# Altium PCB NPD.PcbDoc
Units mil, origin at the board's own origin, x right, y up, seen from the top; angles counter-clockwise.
Board outline 2010.03 x 1675.03 mil, 4 copper layers (Top Layer, VCC, VEE, Bottom Layer); 32 components, 16 nets, 87 pads, 24 vias.
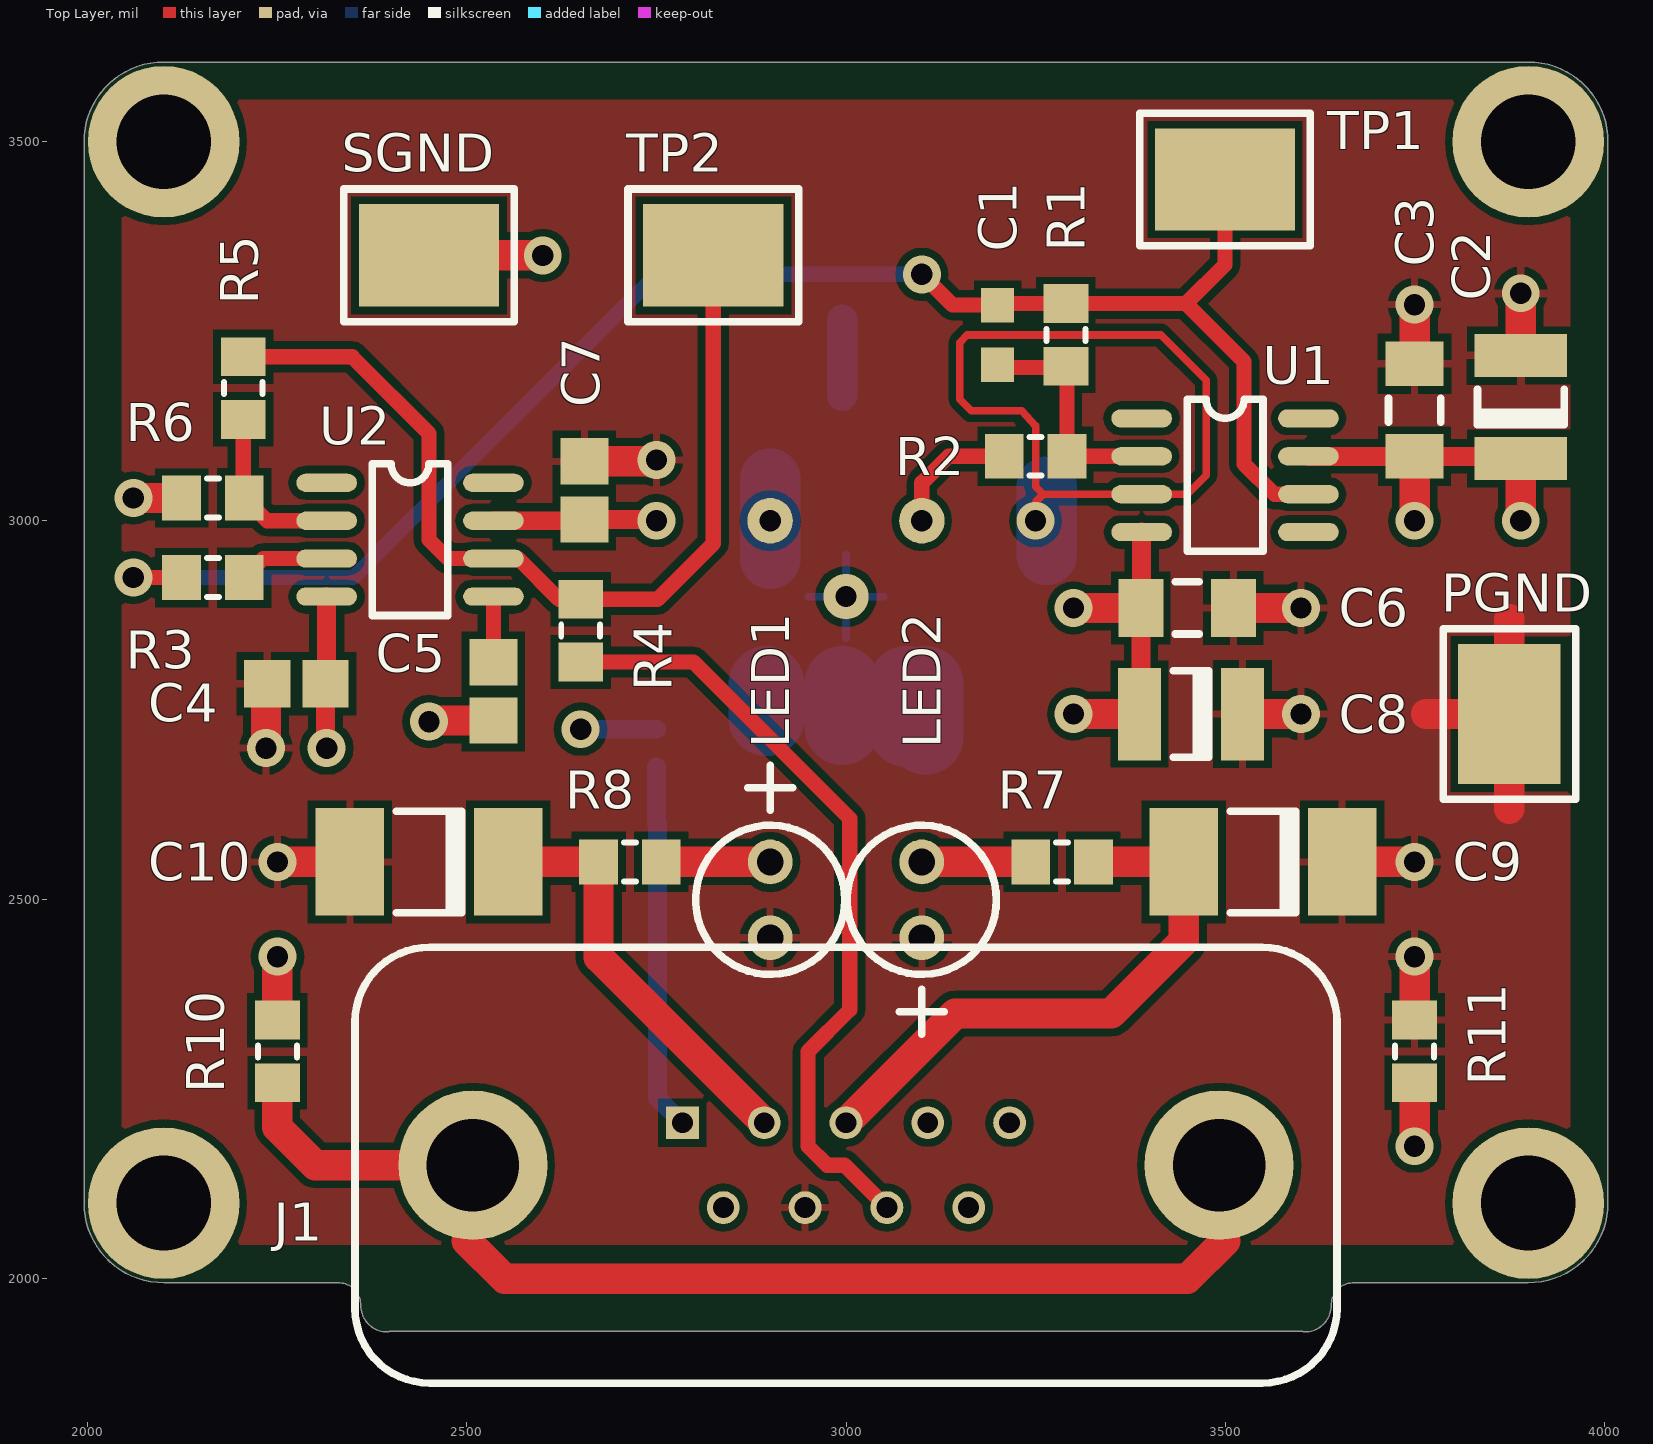
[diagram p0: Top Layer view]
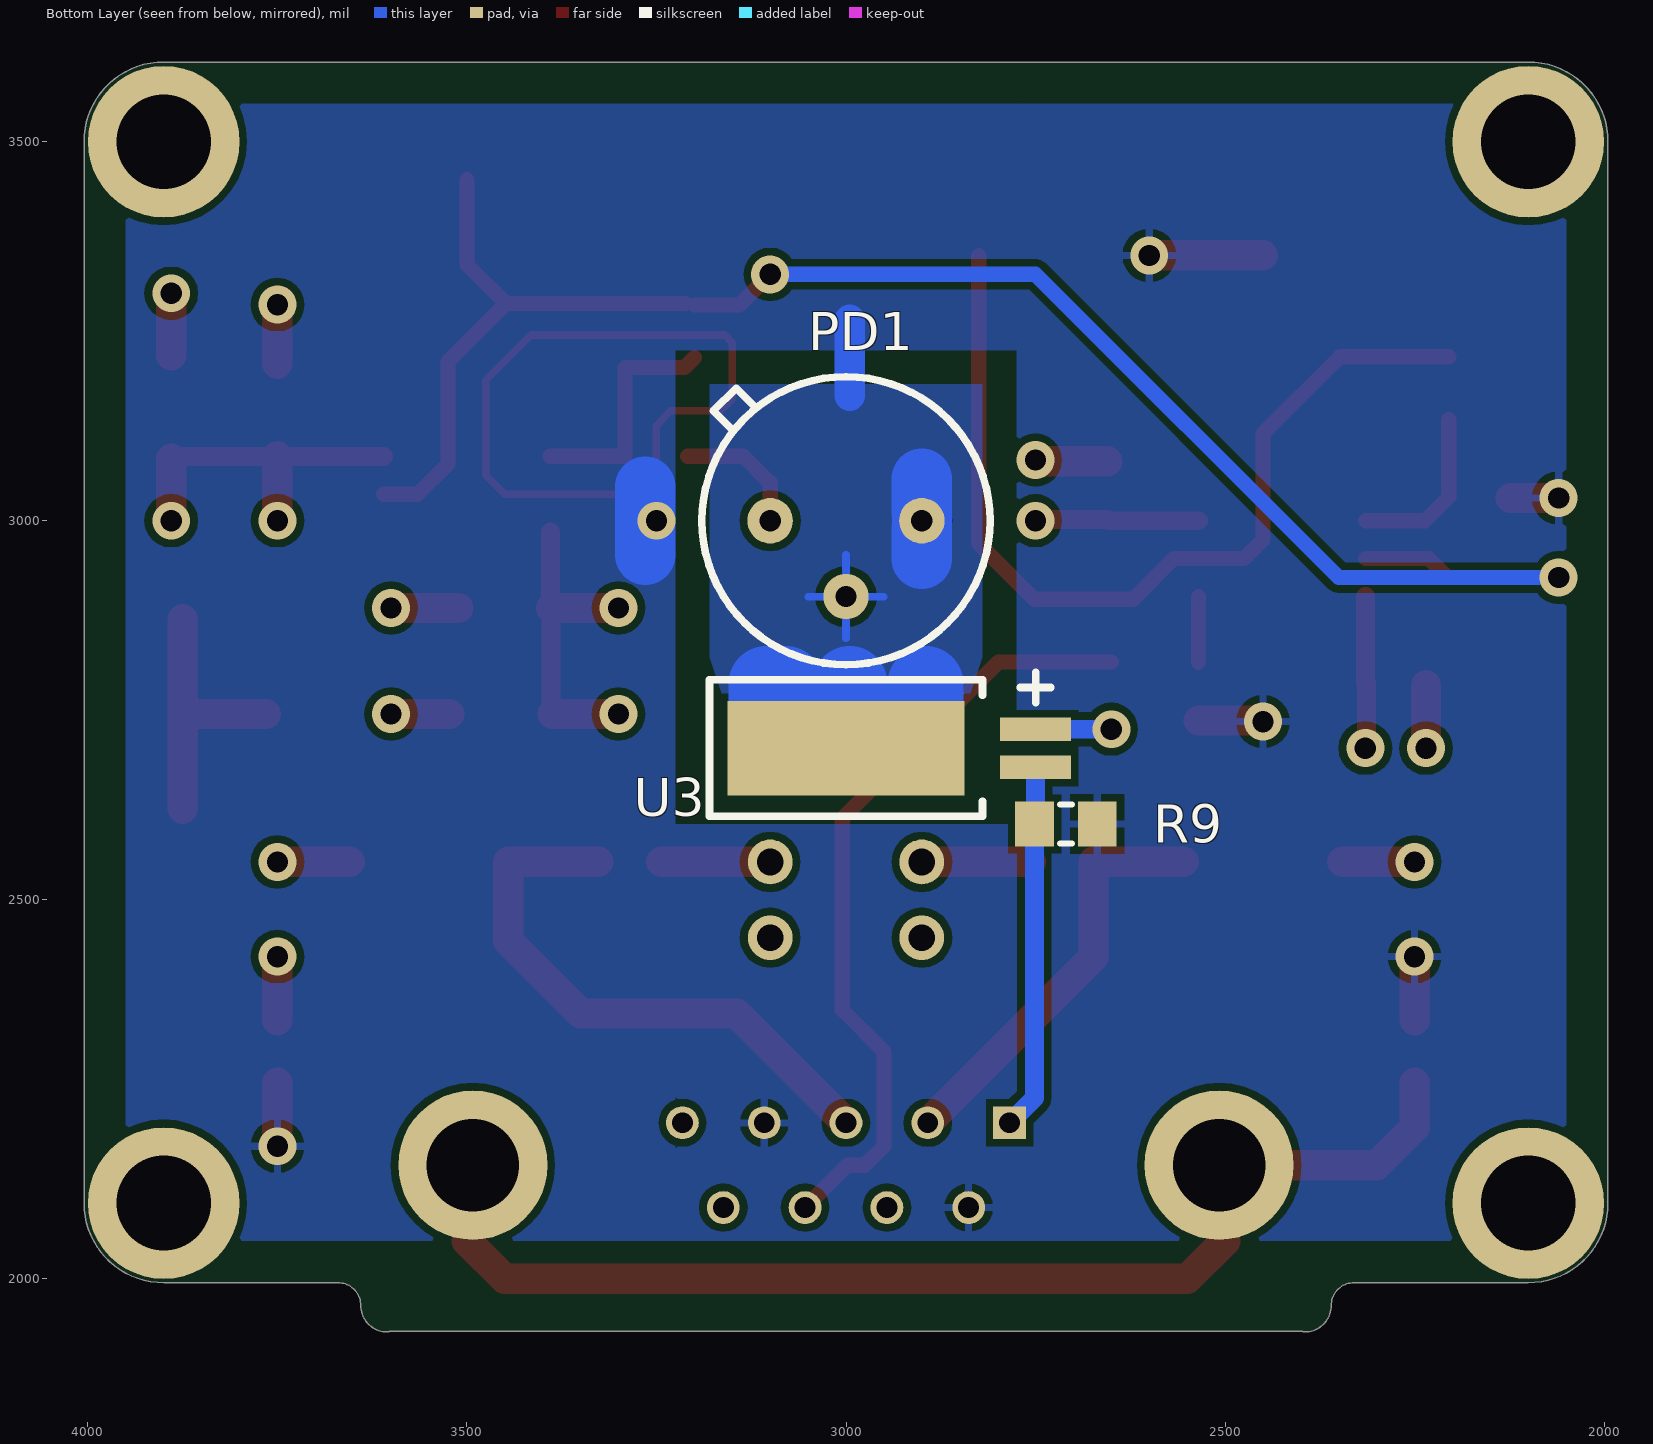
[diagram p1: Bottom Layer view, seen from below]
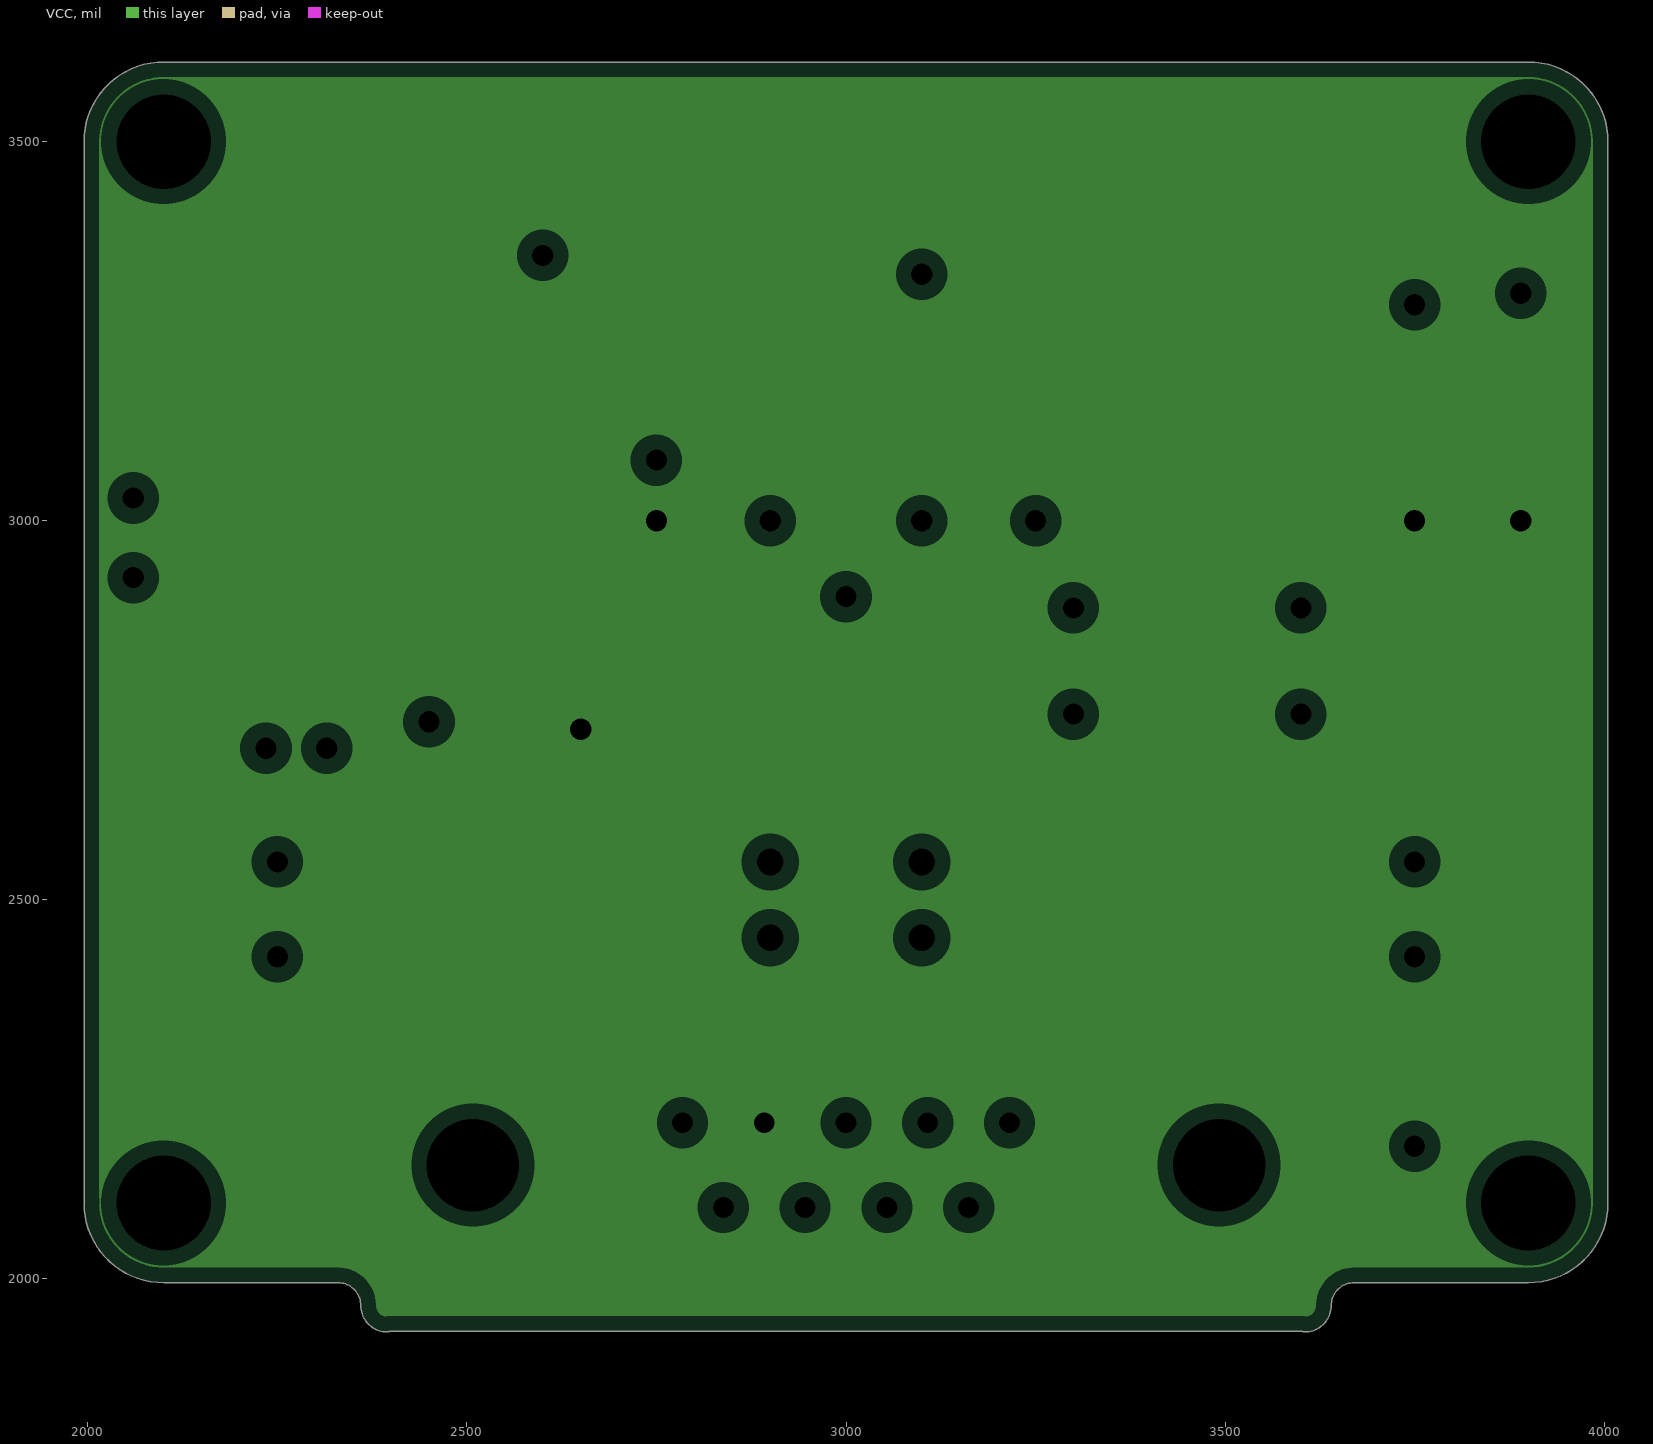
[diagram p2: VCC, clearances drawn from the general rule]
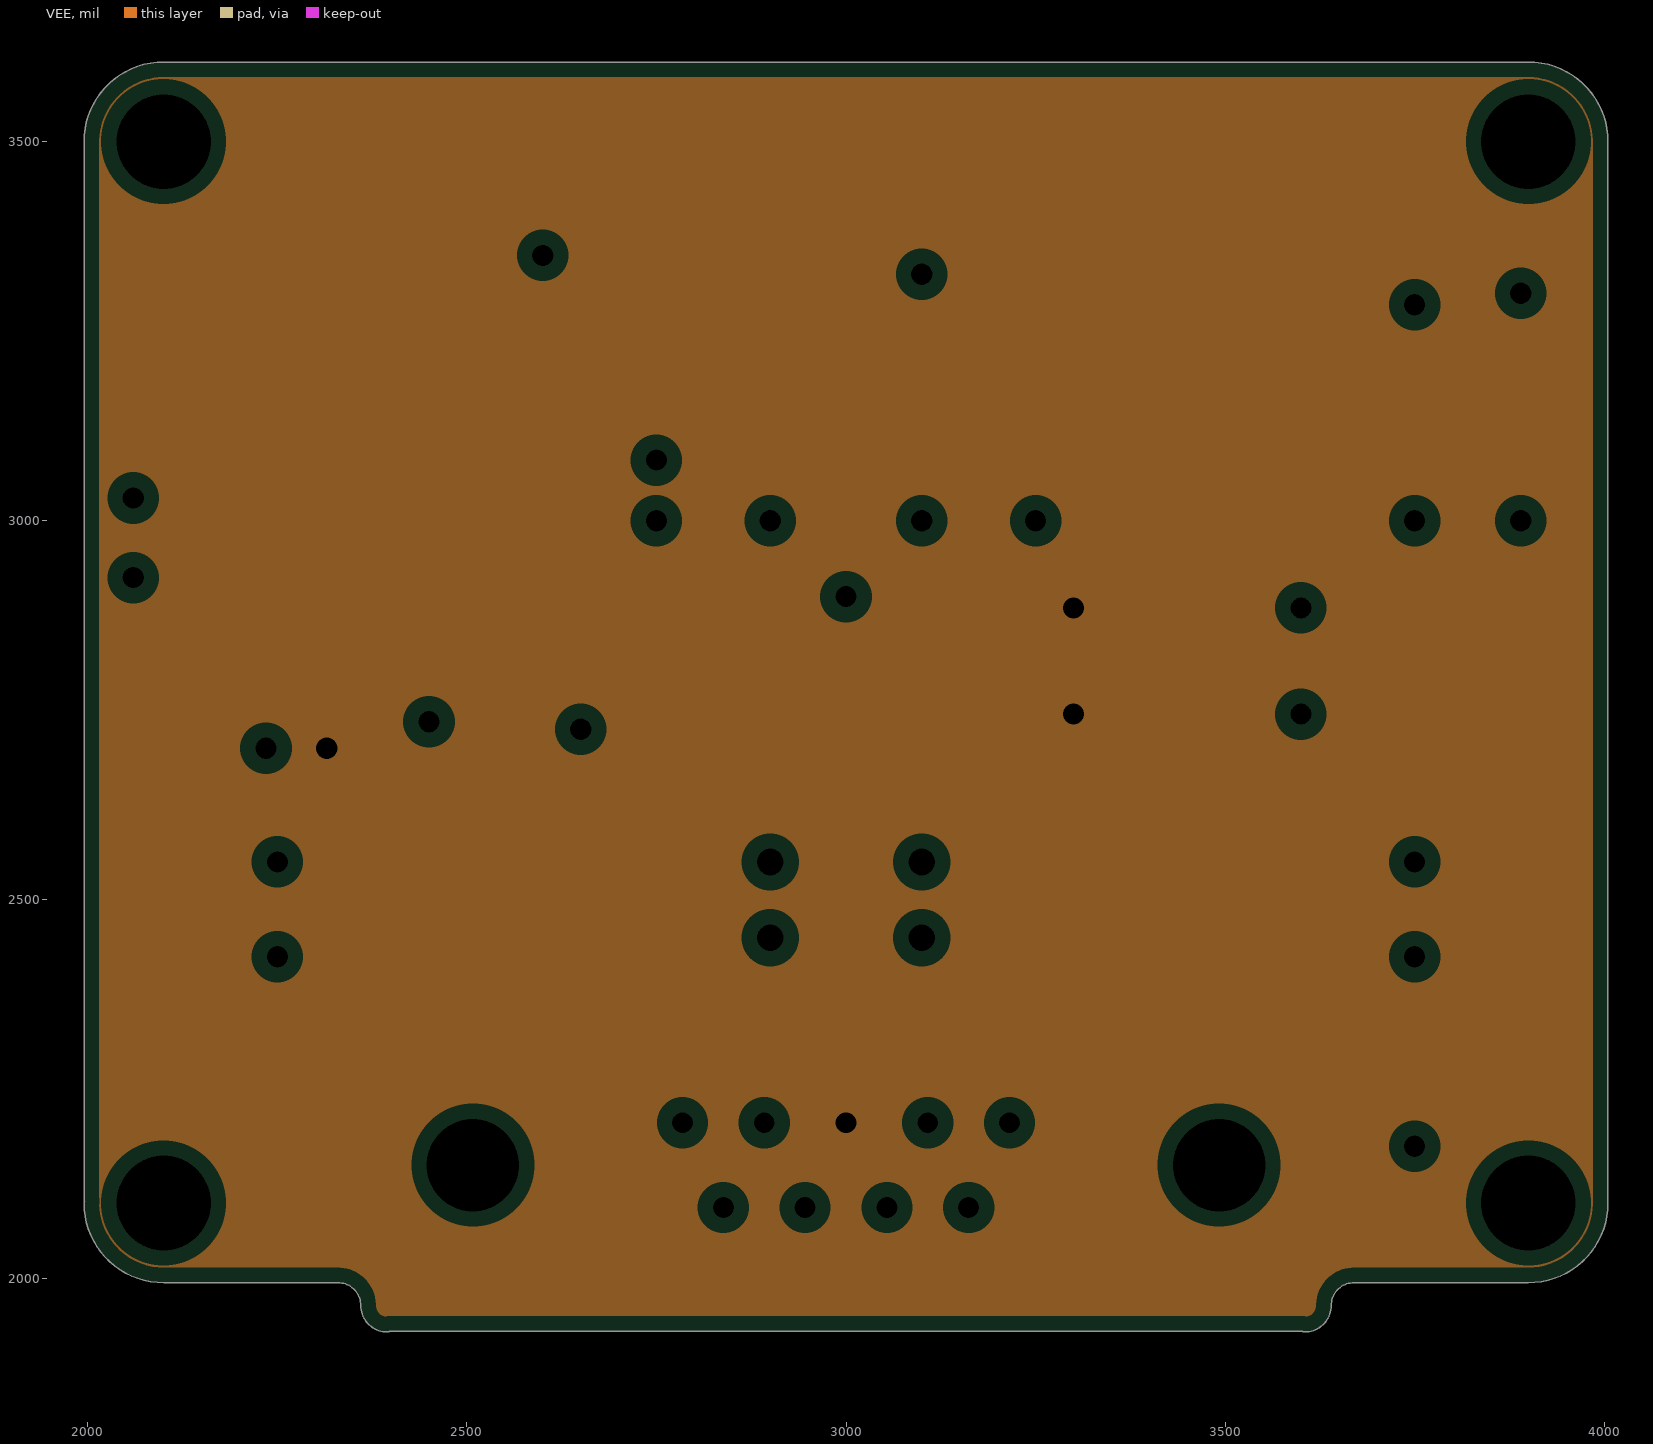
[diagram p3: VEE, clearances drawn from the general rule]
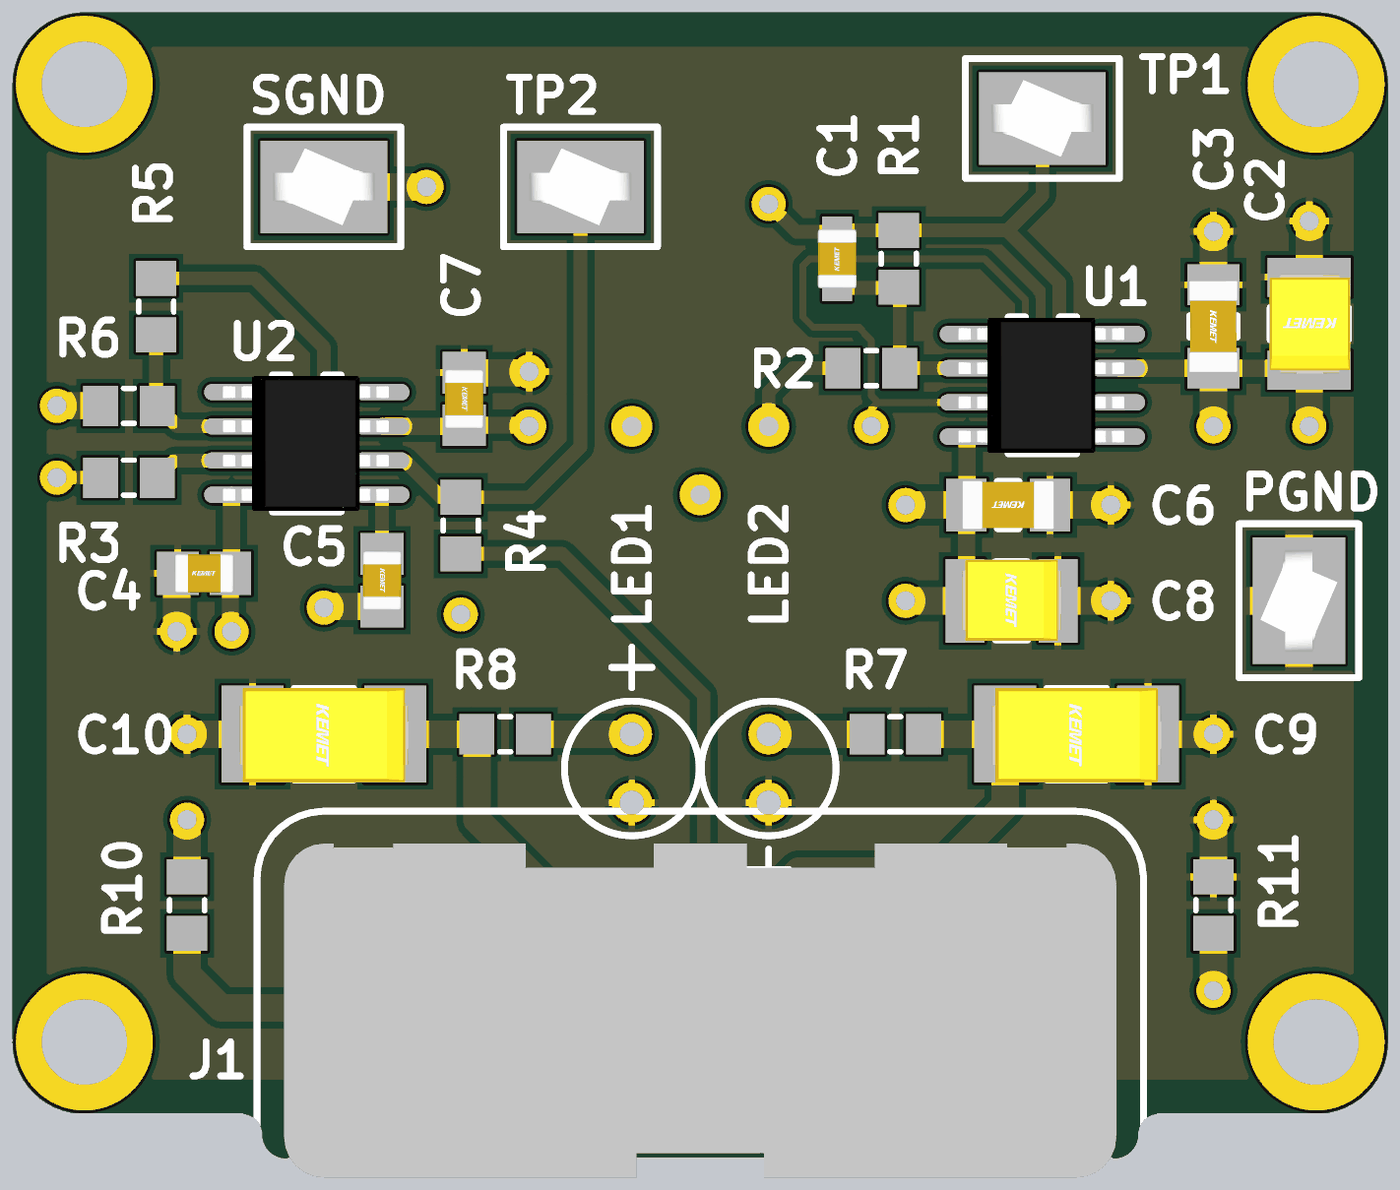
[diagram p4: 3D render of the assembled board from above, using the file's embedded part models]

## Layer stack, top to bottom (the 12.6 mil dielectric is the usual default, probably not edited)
Top Layer: signal copper 1.4
Dielectric: core 12.6, FR-4, Dk 4.8
VCC: plane copper 1.4, net VCC
Dielectric: prepreg 12.6, FR-4, Dk 4.8
VEE: plane copper 1.4, net VEE
Dielectric: core 12.6, FR-4, Dk 4.8
Bottom Layer: signal copper 1.4

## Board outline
2100,1994.98 2330,1994.98 cw(c2330,1965) 2359.99,1965 ccw(c2395,1965) 2395,1929.98 ccw(c2395,1935) 2398.09,1931.05 3601.91,1931.05 ccw(c3605,1935) 3605,1929.98 ccw(c3605,1965) 3640.01,1965 cw(c3670,1965) 3670,1994.98 3900,1994.98 ccw(c3900,2100) 4005.01,2100 4005.01,3500 ccw(c3900,3500) 3900,3605.01 2100,3605.01 ccw(c2100,3500) 1994.98,3500 1994.98,2105 ccw(c2000,2105) 1995.65,2102.5 ccw(c2000,2100) 1994.98,2100 ccw(c2100,2100)

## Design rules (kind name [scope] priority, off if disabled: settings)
Clearance [All] p1: gap=10
HoleSize [All] p1: absolutevalues=TRUE maxlimit=200 minlimit=1 maxpercent=80.000 minpercent=20.000
PlaneClearance [All] p1: clearance=20
PlaneConnect [All] p1: planeconnectstyle=Relief reliefexpansion=20 reliefentries=4 reliefconductorwidth=10 reliefairgap=10
PolygonConnect [All] p1: connectstyle=Relief reliefconductorwidth=10 reliefentries=4 polygonreliefangle="90 Angle"
RoomDefinition Schematic [InComponentClass('Schematic')] p1: confinementstyle=ConfineOut formatcopy=TRUE lockcomponents=FALSE outline 2000,1930 2050,1930 2050,1950 2000,1950
RoutingVias [All] p1: holewidth=28 width=50 viastyle="Through Hole" minholewidth=28 minwidth=50 maxholewidth=28 maxwidth=50
SilkscreenOverComponentPads [All] p1: minsilkscreentomaskgap=10
SolderMaskExpansion [All] p1: expansion=4
Width [All] p1: maxlimit=200 minlimit=10 preferedwidth=10 minimp=50.000000 maximp=50.000000 favimp=50.000000
24 further rules are at their usual default settings.

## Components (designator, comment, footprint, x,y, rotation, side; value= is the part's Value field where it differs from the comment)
C1 "2.7 pF" "Kemet 0805, low density" 3200,3245 r90 top
C2 "3.3 uF" "Kemet 3528-21" 3890,3150 r90 top
C3 "0.1 uF" "Kemet EIA 1206" 3750,3146 r270 top
C4 "0.1 uF" "0805 low density" 2275,2785 r0 top
C5 "68 pF" "Kemet EIA 0805" 2535,2775 r270 top
C6 "0.1 uF" "Kemet EIA 1206" 3450,2885 r180 top
C7 "0.1 uF" "0805 low density" 2655,3040 r270 top
C8 "3.3 uF" "Kemet 3528-21" 3455,2745 r180 top
C9 "10 uF" "Kemet 6032-28" 3550,2550 r180 top
C10 "10 uF" "Kemet 6032-28" 2450,2550 r180 top
J1 "Dsub 9 male" 1-338309 3000,2150 r0 top
LED1 "3mm LED" WP424GDT 2900,2500 r270 top
LED2 "3mm LED" WP424GDT 3100,2500 r90 top
PD1 "C30665GH" TO-5 3000,3000 r0 bottom
PGND "GROUND TEST POINT" "COMPACT TEST POINT" 3875,2745 r90 top (schematic designator TP3)
R1 "20.0k" "Vishay TNPW0805 e3 low density" 3290,3245 r90 top
R2 "ZERO" "Vishay TNPW0805 e3 low density" 3250,3085 r0 top
R3 "ZERO" "Vishay TNPW0805 e3 low density" 2165,2925 r0 top
R4 "ZERO" "Vishay TNPW0805 e3 low density" 2650,2855 r270 top
R5 "ZERO" "Vishay TNPW0805 e3 low density" 2205,3175 r90 top
R6 "ZERO" "Vishay TNPW0805 e3 low density" 2165,3030 r0 top
R7 "2.00k" "Vishay TNPW0805 e3 low density" 3285,2550 r0 top
R8 "2.00k" "Vishay TNPW0805 e3 low density" 2715,2550 r180 top
R9 "10.0k" "Vishay TNPW0805 e3 low density" 2710,2600 r0 bottom
R10 "ZERO" "Vishay TNPW0805 e3 low density" 2250,2300 r270 top
R11 "ZERO" "Vishay TNPW0805 e3 low density" 3750,2300 r270 top
SGND "GROUND TEST POINT" "COMPACT TEST POINT" 2450,3350 r0 top (schematic designator TP4)
TP1 "TEST POINT" "COMPACT TEST POINT" 3500,3450 r0 top
TP2 "TEST POINT" "COMPACT TEST POINT" 2825,3350 r0 top
U1 "THS4631D" SO-8 3500,3060 r0 top
U2 "AD829ARZ" SO-8 2425,2975 r0 top
U3 "AD590MF" AD590 3000,2700 r0 bottom

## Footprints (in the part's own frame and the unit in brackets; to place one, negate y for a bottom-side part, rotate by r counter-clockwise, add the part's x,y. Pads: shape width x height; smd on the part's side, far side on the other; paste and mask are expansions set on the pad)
1-338309 [mm] "DB9 male, vertical plug header with solder contacts"
  rect 1.1x1.1 hole 0.7: 1(-5.48,1.42)
  round 1.1 hole 0.7: 2(-2.74,1.42) 3(0,1.42) 4(2.74,1.42) 5(5.48,1.42) 6(-4.11,-1.42) 7(-1.37,-1.42) 8(1.37,-1.42) 9(4.11,-1.42)
  round 5 hole 3.1: 10(-12.5,0) 11(12.5,0)
  silkscreen extent -16.45,-7.3 16.45,7.3, body extent -15.45,-6.3 15.45,6.1, height 12.1
"0805 low density" [mm] "0805 chip capacitor, 2 leads, body 2.0x1.3 mm, low density"
  rect 1.55x1.6 smd: 1(-0.975,0) 2(0.975,0)
  body extent -1.1,-0.73 1.1,0.72, height 0.87
AD590 [mil] "2 lead ceramic flat package (F-2)"
  rect 93.75x31.25 smd: 1(-250,-25) 2(-250,25)
  rect 312.5x125 smd: 3(0,0)
  silkscreen extent -270,-100 180,90, body extent -300,-46 105,46, height 50
"COMPACT TEST POINT" [mil] "compact SMT test point"
  rect 185x135 smd: 1(0,0)
  silkscreen extent -112,-88 112,88, body extent -75,-56 75,56, height 91
"Kemet 0805, low density" [mm] "0805 low density chip capacitor"
  rect 1.15x1.1 smd: 1(-1,0) 2(1,0)
  body extent -1.1,-0.73 1.1,0.72, height 0.87
"Kemet 3528-21" [mm] "2 lead, polarised chip capacitor, body 3.5 mm x 2.8 mm, IPC low density"
  rect 1.45x3.1 smd: 1(-1.725,0) 2(1.725,0)
  silkscreen extent -0.6,-1.45 0.6,1.45, body extent -1.85,-1.52 1.85,1.48, height 2.11
"Kemet 6032-28" [mm] "2 lead, polarised chip capacitor, body 6.0 mm x 3.2 mm, IPC low density"
  rect 2.3x3.6 smd: 1(-2.65,0) 2(2.65,0)
  silkscreen extent -1.1,-1.7 1.1,1.7, body extent -3.15,-1.71 3.15,1.79, height 2.81
"Kemet EIA 0805" [mm] "2 lead, chip capacitor, body 2.00 mm x 1.25mm, IPC low density"
  rect 1.55x1.6 smd: 1(-0.975,0) 2(0.975,0)
  body extent -1.09,-0.72 1.11,0.72, height 0.87
"Kemet EIA 1206" [mm] "2 lead, chip capacitor, body 3.2 mm x 1.60 mm, IPC low density"
  rect 1.5x1.95 smd: 1(-1.55,0) 2(1.549,0)
  silkscreen extent -0.4,-0.87 0.4,0.87, body extent -1.7,-0.9 1.7,0.9, height 0.88
SO-8 [mil] "8 pin small outline package"
  oval 80x24 smd: 1(-110,75) 2(-110,25) 3(-110,-25) 4(-110,-75) 5(110,-75) 6(110,-25) 7(110,25) 8(110,75)
  silkscreen extent -50,-100 50,100, body extent -123,-98 120,98, height 79
TO-5 [mil] "3 pin TO-5"
  round 60 hole 28: 1(100,0) 2(0,100) 3(-100,0)
  silkscreen extent -190,-190 190,190, body extent -179,-180 179,180, height 167
"Vishay TNPW0805 e3 low density" [mm] "chip resistor, 2 lead, 0805 body 2.0 x 1.3 mm, IPC low density"
  rect 1.3x1.5 smd: 1(-1.05,0) 2(1.05,0)
  silkscreen extent -0.2,-0.65 0.2,0.65, body extent -1,-0.63 1,0.63, height 0.45
WP424GDT [mm] "T-1 (3 mm) cylindrical LED lamp"
  round 1.5 hole 0.9: A(-1.27,0) K(1.27,0)
  silkscreen extent -4.5,-2.5 2.5,2.5, body extent -1.7,-1.7 1.69,1.69, height 6

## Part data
C1: library part "2.7 pF, 50 V, 0805 ceramic capacitor", "2.7 pF, +/- 0.1 pF C0G ceramic chip capacitor"
C2 C8: library part "3.3 uF, 35 V, 10% tantalum capacitor", "SMD chip tantalum capacitor"
C3 C6: library part "0.1 uF, 50 V, 1206 ceramic capacitor", "0.1 uF, +/- 1% U2J ceramic chip capacitor"
C4 C7: library part "0.1 uF, 5% 50 V, 0805 ceramic capacitor", "0.1 uF, +/- 5% X7R ceramic chip capacitor"
C5: library part "68 pF, 50 V, 0805 ceramic capacitor", "68 pF, +/- 1% C0G ceramic chip capacitor"
C9 C10: library part "10 uF, 25 V, 10% tantalum capacitor", "SMD chip tantalum capacitor"
J1: "Dsub 9 male, vertical"
PD1: "3 mm InGaAs photodiode"
R1: library part "20.0k ohm, +/- 0.05%", "20.0k ohm, +/- 0.05% thin film chip resistor"
R2 R3 R4 R5 R6 R10 R11: library part "ZERO OHMS", "1206 zero ohm jumper"
R7 R8: library part "2.00k ohm, +/- 0.05%", "2.00k ohm, +/- 0.05% thin film chip resistor"
R9: library part "10.0k ohm, +/- 0.05%", "10.0k ohm, +/- 0.05% thin film chip resistor"
TP1 TP2: library part TP, "test point"
U1: "high voltage, high slew rate, wideband FET input operational amplifier"
U2: "high speed, low noise video op amp"
U3: "2 terminal IC temperature transducer"

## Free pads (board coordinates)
  round 200 hole 125: ""(2100,2100) ""(2100,3500) ""(3900,2100) ""(3900,3500)

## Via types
v1: diameter 50, hole 28, Top Layer to Bottom Layer, 24 vias

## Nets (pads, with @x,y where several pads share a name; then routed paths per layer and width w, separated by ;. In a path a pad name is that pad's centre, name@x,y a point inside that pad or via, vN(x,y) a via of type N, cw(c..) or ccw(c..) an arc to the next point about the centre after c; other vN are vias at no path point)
BUFFOUT: J1.8 R4.2 | length 1034.1
  Top Layer w20: R4.2 2798.66,2813.66 3005,2607.32 3005,2355 2950,2300 2950,2175 2975,2150 2998.03,2150 J1.8 J1.8@3052.9,2094.09
NetC1_1: C1.1 R1.1 R2.2 U1.2 | length 312.8
  Top Layer w20: C1.1@3200,3215.47 3213.15,3202.32 3291.34,3202.32 R2.2 U1.2
NetC1_2: C1.2 R1.2 R3.1 TP1.1 U1.6 | length 2152.5
  Top Layer w20: v1(2060,2925) R3.1 ; v1(3100,3325) 3140.63,3284.37 C1.2 ; C1.2@3211.81,3286.34 R1.2 3448.66,3286.34 ; TP1.1 3500,3337.68 3448.66,3286.34 ; U1.6 3565,3035 3525,3075 3525,3210 3448.66,3286.34
  Bottom Layer w20: v1(2060,2925) 2350,2925 2750,3325 v1(3100,3325)
NetC5_1: C5.1 U2.5 | length 86.6
  Top Layer w20: C5.1 U2.5
NetJ1_10: J1.10 J1.11 R10.2 | length 1579.3
  Top Layer w40: R10.2 2250,2200 2300,2150 J1.10 2500,2050 2550,2000 3450,2000 3500,2050 J1.11
NetLED1_A: LED1.A R8.1 | length 143.7
  Top Layer w40: R8.1 LED1.A
NetLED2_K: LED2.K R7.1 | length 143.7
  Top Layer w40: LED2.K R7.1
NetPD1_1: PD1.1 R2.1 | length 173.2
  Top Layer w20: PD1.1 3100,3050 3135,3085 R2.1
NetR3_2: R3.2 U2.3 | length 119
  Top Layer w20: R3.2 2231.34,2950 U2.3
NetR4_1: R4.1 R5.2 TP2.1 U2.6 | length 1245.1
  Top Layer w20: R5.2 2348.66,3216.34 2450,3115 2450,2975 2475,2950 U2.6 2567.68,2950 2621.34,2896.34 R4.1 2751.34,2896.34 2825,2970 TP2.1
NetR5_1: R5.1 R6.2 U2.2 | length 223.4
  Top Layer w20: R6.2@2205,3031.34 R5.1 ; R6.2 2236.34,3000 U2.2
PGND: C2.2 C3.1 C4.1 C6.1 C7.1 C8.1 C9.1 C10.2 J1.7 LED1.K LED2.A PGND.1 R11.1 | length 1137.9
  Top Layer w40: v1(2235,2700) C4.1@2235,2783.39 ; v1(2250,2550) C10.2 ; C7.1 v1@2748.39,3078.39 ; C6.1 v1(3600,2885) ; C8.1 v1(3600,2745) ; C9.1 v1(3750,2550) ; R11.1 v1(3750,2425) ; C3.1 v1(3750,3285) ; 3765,2745 PGND.1 ; 3875,2620 3875,2870 ; C2.2 v1(3890,3300)
  other v1: 2750,3080
TEMPOUT: J1.1 R9.2 U3.2 | length 481.4
  Bottom Layer w25: R9.2@2750,2601.34 U3.2 ; R9.2 2751.34,2238.82 J1.1
THERMALPAD: C5.2 J1.4 J1.6 PD1.2 PD1.3 R6.1 R9.1 R10.1 R11.2 SGND.1 U1.3 U3.3 | length 2231.8
  Top Layer w10: v1(2450,2735) v1@2451.61,2736.61 ; v1(3250,3000) 3250,3025 3260,3035 ; 3260,3035 3250,3045 3250,3125 3231.72,3145 3165,3145 3150,3160 3150,3235 3160,3245 3415,3245 3475,3185 3475,3060 3450,3035 U1.3 3320,3035 3260,3035
  Top Layer w40: v1(2060,3030) R6.1 ; R10.1 v1(2250,2425) ; SGND.1 v1(2600,3350) ; v1@2451.61,2736.61 C5.2 ; v1(3750,2175) R11.2
  Bottom Layer w10: 2950,2900 3050,2900 ; 3000,2845 3000,2955
  Bottom Layer w40: 2995,3165 2995,3265
  Bottom Layer w80: 2900,2950 2900,3055 ; 3265,2955 3265,3045
  Bottom Layer w100: U3.3@2895,2740 2895,2785 ; U3.3@2995,2727.5 2995,2785 ; U3.3@3080,2725 3080,2785 ; U3.3@3105,2715 3105,2785
VCC: C2.1 C3.2 C7.2 C10.1 J1.2 R8.2 U1.7 U2.7 U3.1 | length 1322.5
  Top Layer w20: C3.2 C3.2@3757.91,3077.09
  Top Layer w25: U2.7 C7.2@2653.98,3000 ; C7.2 v1@2748.39,3001.61 ; U1.7 C3.2 C2.1@3887.91,3085
  Top Layer w40: C10.1 R8.2 2673.66,2424.37 J1.2 ; v1(3750,3000) C3.2 ; v1(3890,3000) C2.1
  Bottom Layer w25: v1(2650,2725) U3.1
  other v1: 2750,3000
VEE: C4.2 C6.2 C8.2 C9.2 J1.3 R7.2 U1.4 U2.4 | length 1379.2
  Top Layer w25: v1@2313.39,2701.61 C4.2 ; C4.2@2315,2786.02 U2.4 ; C8.2@3388.98,2746.89 C6.2 ; C6.2@3390,2886.02 U1.4
  Top Layer w40: J1.3 3144.09,2350 3350,2350 3445.67,2445.67 C9.2 R7.2 ; v1(3300,2745) C8.2 ; v1(3300,2885) C6.2
  other v1: 2315,2700
pads on no net: J1.5 J1.9 U1.1 U1.5 U1.8 U2.1 U2.8

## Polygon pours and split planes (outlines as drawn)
THERMALPAD on Bottom Layer "Bottom Layer-No Net" (solid, pour order 1004): 2775,2050 3225,2050 3225,2600 2775,2600 2775,2050
THERMALPAD on Bottom Layer "Bottom Layer-No Net" (solid, pour order 1003): 2775,3548.84 2776.16,3550 3225,3550 3225,3225 2775,3225 2775,3548.84
THERMALPAD on Bottom Layer "Bottom Layer-No Net" (solid, pour order 1002): 3950,3400 3800,3550 3225,3550 3225,2050 3800,2050 3950,2200 3950,3400
THERMALPAD on Bottom Layer "Bottom Layer-No Net" (solid, pour order 1001): 2050,3400 2200,3550 2775,3550 2775,2050 2200,2050 2050,2200 2050,3400
THERMALPAD on Bottom Layer "Bottom Layer-No Net" (solid, pour order 1000): 3160,2760 2840,2760 2820,2820 2820,3180 3180,3180 3180,2820 3160,2760
no net on Bottom Solder "Bottom Layer-No Net" (solid): 3160,2765 3160,2800 3180,2820 3180,3180 2820,3180 2820,2820 2840,2800 2840,2765 3160,2765
PGND on Top Layer "Bottom Layer-No Net" (solid, pour order 1001): 2200,2045 2045,2200 2045,3405 2200,3555 3805,3555 3955,3405 3955,2195 3805,2045 2200,2045
VCC on VCC (split plane): 152 vertices, not listed, extent 2015.03,1950.27 3984.97,3584.97
VEE on VEE (split plane): 152 vertices, not listed, extent 2015.03,1950.27 3984.97,3584.97

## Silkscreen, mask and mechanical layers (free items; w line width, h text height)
Mechanical 1:
  lines w7.87: 2395,1935 3605,1935
  lines w10: 2000,2100 ccw(c2100,2100) 2100,2000 2330,2000 cw(c2330,1965) 2365,1965 ccw(c2395,1965) 2395,1935 ; 2000,2105 2000,3500 cw(c2100,3500) 2100,3600 3900,3600 cw(c3900,3500) 4000,3500 4000,2100 cw(c3900,2100) 3900,2000 3670,2000 ccw(c3670,1965) 3635,1965 cw(c3605,1965) 3605,1935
